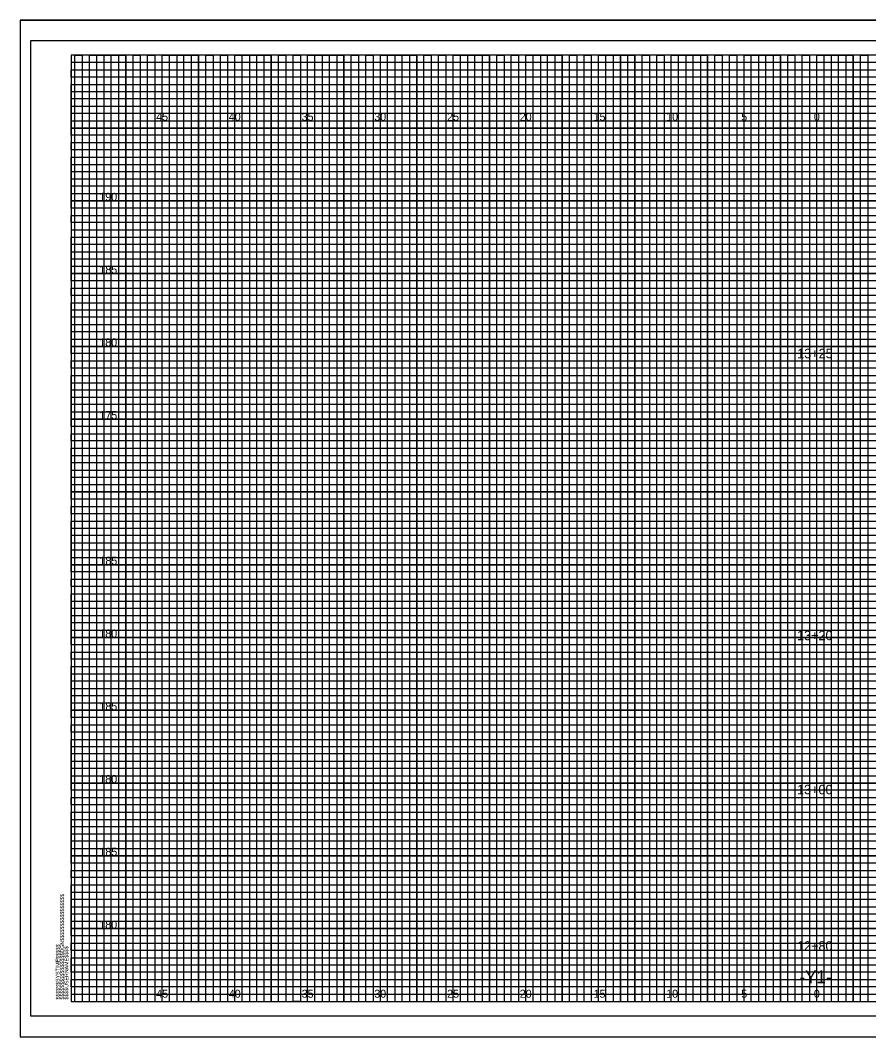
# Model space of a CAD drawing. Extents: x -4 to 103, y -2 to 209.
# Drawn here: x -3.5 to 54.8, y 68.4 to 138.2 of the extents above; entities that cross this region are included whole.
import ezdxf

# ---------------------------------------------------------------- set-up
doc = ezdxf.new("R2010")
doc.units = 0
for name, color, linetype in [('Old_Level_10', 7, 'Continuous'), ('Old_Level_16', 7, 'Continuous'), ('Old_Level_3', 7, 'Continuous'), ('Old_Level_4', 7, 'Continuous'), ('Old_Level_5', 7, 'Continuous'), ('Old_Level_6', 7, 'Continuous'), ('Old_Level_8', 7, 'Continuous'), ('Prop Dimension', 7, 'Continuous'), ('Prop XS Dump Level', 7, 'Continuous'), ('Prop XS Finish Grade Pavement', 7, 'Continuous'), ('Prop XS Subgrade Earthwork', 7, 'Continuous')]:
    doc.layers.add(name, color=color, linetype=linetype)

msp = doc.modelspace()

# ---------------------------------------------------------------- linework, layer by layer
at = {"layer": 'Old_Level_10'}
for p, q in [((1.25, 70.825), (1.25, 135.825)), ((3.75, 70.825), (3.75, 135.825)), ((6.25, 70.825), (6.25, 135.825)), ((8.75, 70.825), (8.75, 135.825)), ((11.25, 70.825), (11.25, 135.825)), ((13.75, 70.825), (13.75, 135.825)), ((16.25, 70.825), (16.25, 135.825)), ((18.75, 70.825), (18.75, 135.825)), ((21.25, 70.825), (21.25, 135.825)), ((23.75, 70.825), (23.75, 135.825)), ((26.25, 70.825), (26.25, 135.825)), ((28.75, 70.825), (28.75, 135.825)), ((31.25, 70.825), (31.25, 135.825)), ((33.75, 70.825), (33.75, 135.825)), ((36.25, 70.825), (36.25, 135.825)), ((38.75, 70.825), (38.75, 135.825)), ((41.25, 70.825), (41.25, 135.825)), ((43.75, 70.825), (43.75, 135.825)), ((46.25, 70.825), (46.25, 135.825)), ((48.75, 70.825), (48.75, 135.825)), ((51.25, 70.825), (51.25, 135.825)), ((53.75, 70.825), (53.75, 135.825)), ((0, 133.325), (74.25, 133.325)), ((0, 130.825), (102.5, 130.825)), ((0, 128.325), (102.5, 128.325)), ((0, 125.825), (102.5, 125.825)), ((0, 123.325), (102.5, 123.325)), ((0, 120.825), (102.5, 120.825)), ((0, 118.325), (102.5, 118.325)), ((0, 115.825), (102.5, 115.825)), ((0, 113.325), (102.5, 113.325)), ((0, 110.825), (102.5, 110.825)), ((0, 108.325), (102.5, 108.325)), ((0, 105.825), (102.5, 105.825)), ((0, 103.325), (102.5, 103.325)), ((0, 100.825), (102.5, 100.825)), ((0, 98.325), (102.5, 98.325)), ((0, 95.825), (102.5, 95.825)), ((0, 93.325), (102.5, 93.325)), ((0, 90.825), (102.5, 90.825)), ((0, 88.325), (102.5, 88.325)), ((0, 85.825), (102.5, 85.825)), ((0, 83.325), (102.5, 83.325)), ((0, 80.825), (102.5, 80.825)), ((0, 78.325), (102.5, 78.325)), ((0, 75.825), (102.5, 75.825)), ((0, 73.325), (102.5, 73.325))]:
    msp.add_line(p, q, dxfattribs=at)
at = {"layer": 'Old_Level_3'}
for p, q in [((-3.5, 138.225), (103.4, 138.225)), ((-3.5, 138.225), (-3.5, 68.4)), ((-3.5, 68.4), (103.4, 68.4))]:
    msp.add_line(p, q, dxfattribs=at)
at = {"layer": 'Old_Level_4'}
msp.add_lwpolyline([(103, 136.825), (-2.8, 136.825), (-2.8, 69.825), (103, 69.825)], close=True, dxfattribs=at)
at = {"layer": 'Old_Level_5'}
msp.add_lwpolyline([(103.4, 138.225), (-3.5, 138.225), (-3.5, 68.4), (103.4, 68.4)], close=True, dxfattribs=at)
at = {"layer": 'Old_Level_6'}
msp.add_lwpolyline([(102.5, 135.825), (0, 135.825), (0, 70.825), (102.5, 70.825)], close=True, dxfattribs=at)
at = {"layer": 'Old_Level_8'}
for points in [[(1.25, 70.825), (1.25, 135.825), (3.75, 135.825), (3.75, 70.825), (6.25, 70.825), (6.25, 135.825), (8.75, 135.825), (8.75, 70.825), (11.25, 70.825), (11.25, 135.825), (13.75, 135.825), (13.75, 70.825), (16.25, 70.825), (16.25, 135.825), (18.75, 135.825), (18.75, 70.825), (21.25, 70.825), (21.25, 135.825), (23.75, 135.825), (23.75, 70.825), (26.25, 70.825), (26.25, 135.825), (28.75, 135.825), (28.75, 70.825), (31.25, 70.825), (31.25, 135.825), (33.75, 135.825), (33.75, 70.825), (36.25, 70.825), (36.25, 135.825), (38.75, 135.825), (38.75, 70.825), (41.25, 70.825), (41.25, 135.825), (43.75, 135.825), (43.75, 70.825), (46.25, 70.825), (46.25, 135.825), (48.75, 135.825), (48.75, 70.825), (51.25, 70.825), (51.25, 135.825), (53.75, 135.825), (53.75, 70.825)], [(102.5, 130.825), (0, 130.825), (0, 133.325), (74.25, 133.325)], [(102.5, 125.825), (0, 125.825), (0, 128.325), (102.5, 128.325)], [(102.5, 120.825), (0, 120.825), (0, 123.325), (102.5, 123.325)], [(102.5, 115.825), (0, 115.825), (0, 118.325), (102.5, 118.325)], [(102.5, 110.825), (0, 110.825), (0, 113.325), (102.5, 113.325)], [(102.5, 105.825), (0, 105.825), (0, 108.325), (102.5, 108.325)], [(102.5, 100.825), (0, 100.825), (0, 103.325), (102.5, 103.325)], [(102.5, 95.825), (0, 95.825), (0, 98.325), (102.5, 98.325)], [(102.5, 90.825), (0, 90.825), (0, 93.325), (102.5, 93.325)], [(102.5, 85.825), (0, 85.825), (0, 88.325), (102.5, 88.325)], [(102.5, 80.825), (0, 80.825), (0, 83.325), (102.5, 83.325)], [(102.5, 75.825), (0, 75.825), (0, 78.325), (102.5, 78.325)], [(0, 73.325), (102.5, 73.325)]]:
    msp.add_lwpolyline(points, dxfattribs=at)
at = {"layer": 'Prop Dimension'}
for points in [[(0.25, 70.825), (0.25, 135.825), (0.75, 135.825), (0.75, 70.825), (1.75, 70.825), (1.75, 135.825), (2.25, 135.825), (2.25, 70.825), (2.75, 70.825), (2.75, 135.825), (3.25, 135.825), (3.25, 70.825), (4.25, 70.825), (4.25, 135.825), (4.75, 135.825), (4.75, 70.825), (5.25, 70.825), (5.25, 135.825), (5.75, 135.825), (5.75, 70.825), (6.75, 70.825), (6.75, 135.825), (7.25, 135.825), (7.25, 70.825), (7.75, 70.825), (7.75, 135.825), (8.25, 135.825), (8.25, 70.825), (9.25, 70.825), (9.25, 135.825), (9.75, 135.825), (9.75, 70.825), (10.25, 70.825), (10.25, 135.825), (10.75, 135.825), (10.75, 70.825), (11.75, 70.825), (11.75, 135.825), (12.25, 135.825), (12.25, 70.825), (12.75, 70.825), (12.75, 135.825), (13.25, 135.825), (13.25, 70.825), (14.25, 70.825), (14.25, 135.825), (14.75, 135.825), (14.75, 70.825), (15.75, 70.825), (15.25, 70.825), (15.25, 135.825), (15.75, 135.825), (15.75, 70.825), (16.75, 70.825), (16.75, 135.825), (17.25, 135.825), (17.25, 70.825), (17.75, 70.825), (17.75, 135.825), (18.25, 135.825), (18.25, 70.825), (19.25, 70.825), (19.25, 135.825), (19.75, 135.825), (19.75, 70.825), (20.25, 70.825), (20.25, 135.825), (20.75, 135.825), (20.75, 70.825), (21.75, 70.825), (21.75, 135.825), (22.25, 135.825), (22.25, 70.825), (22.75, 70.825), (22.75, 135.825), (23.25, 135.825), (23.25, 70.825), (24.25, 70.825), (24.25, 135.825), (24.75, 135.825), (24.75, 70.825), (25.25, 70.825), (25.25, 135.825), (25.75, 135.825), (25.75, 70.825), (26.75, 70.825), (26.75, 135.825), (27.25, 135.825), (27.25, 70.825), (27.75, 70.825), (27.75, 135.825), (28.25, 135.825), (28.25, 70.825), (29.25, 70.825), (29.25, 135.825), (29.75, 135.825), (29.75, 70.825), (30.25, 70.825), (30.25, 135.825), (30.75, 135.825), (30.75, 70.825)], [(30.75, 70.825), (31.75, 70.825), (31.75, 135.825), (32.25, 135.825), (32.25, 70.825), (32.75, 70.825), (32.75, 135.825), (33.25, 135.825), (33.25, 70.825), (34.25, 70.825), (34.25, 135.825), (34.75, 135.825), (34.75, 70.825), (35.25, 70.825), (35.25, 135.825), (35.75, 135.825), (35.75, 70.825), (36.75, 70.825), (36.75, 135.825), (37.25, 135.825), (37.25, 70.825), (37.75, 70.825), (37.75, 135.825), (37.75, 70.825)], [(38.25, 135.825), (38.25, 70.825), (39.25, 70.825), (39.25, 135.825), (39.75, 135.825), (39.75, 70.825), (40.25, 70.825), (40.25, 135.825), (40.75, 135.825), (40.75, 70.825), (41.75, 70.825), (41.75, 135.825), (42.25, 135.825), (42.25, 70.825), (42.75, 70.825), (42.75, 135.825), (43.25, 135.825), (43.25, 70.825), (43.75, 70.825), (44.25, 70.825), (44.25, 135.825), (44.75, 135.825), (44.75, 70.825), (45.25, 70.825), (45.25, 135.825), (45.75, 135.825), (45.75, 70.825), (46.75, 70.825), (46.75, 135.825), (47.25, 135.825), (47.25, 70.825), (47.75, 70.825), (47.75, 135.825), (48.25, 135.825), (48.25, 70.825), (49.25, 70.825), (49.25, 135.825), (49.75, 135.825), (49.75, 70.825), (50.25, 70.825), (50.25, 135.825), (50.75, 135.825), (50.75, 70.825), (51.75, 70.825), (51.75, 135.825), (52.25, 135.825), (52.25, 70.825), (52.75, 70.825), (52.75, 135.825), (53.25, 135.825), (53.25, 70.825), (54.25, 70.825), (54.25, 135.825), (54.75, 135.825), (54.75, 70.825), (55.25, 70.825)], [(0, 132.825), (0, 133.825), (74.25, 133.825), (74.25, 134.325), (0, 134.325), (0, 134.825), (74.25, 134.825), (74.25, 135.325), (0, 135.325)], [(102.5, 132.825), (0, 132.825)], [(102.5, 131.825), (0, 131.825), (0, 132.325), (102.5, 132.325)], [(102.5, 130.325), (0, 130.325), (0, 131.325), (102.5, 131.325)], [(102.5, 129.325), (0, 129.325), (0, 129.825), (102.5, 129.825)], [(102.5, 127.825), (0, 127.825), (0, 128.825), (102.5, 128.825)], [(102.5, 126.825), (0, 126.825), (0, 127.325), (102.5, 127.325)], [(102.5, 125.325), (0, 125.325), (0, 126.325), (102.5, 126.325)], [(102.5, 124.325), (0, 124.325), (0, 124.825), (102.5, 124.825)], [(0, 123.825), (102.5, 123.825)], [(102.5, 122.825), (0, 122.825)], [(102.5, 121.825), (0, 121.825), (0, 122.325), (102.5, 122.325)], [(102.5, 120.325), (0, 120.325), (0, 121.325), (102.5, 121.325)], [(102.5, 119.325), (0, 119.325), (0, 119.825), (102.5, 119.825)], [(102.5, 117.825), (0, 117.825), (0, 118.825), (102.5, 118.825)], [(102.5, 116.825), (0, 116.825), (0, 117.325), (102.5, 117.325)], [(102.5, 115.325), (0, 115.325), (0, 116.325), (102.5, 116.325)], [(102.5, 114.325), (0, 114.325), (0, 114.825), (102.5, 114.825)], [(102.5, 112.825), (0, 112.825), (0, 113.825), (102.5, 113.825)], [(102.5, 111.825), (0, 111.825), (0, 112.325), (102.5, 112.325)], [(102.5, 110.325), (0, 110.325), (0, 111.325), (102.5, 111.325)], [(102.5, 109.325), (0, 109.325), (0, 109.825), (102.5, 109.825)], [(102.5, 107.825), (0, 107.825), (0, 108.825), (102.5, 108.825)], [(102.5, 106.825), (0, 106.825), (0, 107.325), (102.5, 107.325)], [(102.5, 105.325), (0, 105.325), (0, 106.325), (102.5, 106.325)], [(102.5, 104.325), (0, 104.325), (0, 104.825), (102.5, 104.825)], [(102.5, 102.825), (0, 102.825), (0, 103.825), (102.5, 103.825)], [(102.5, 101.825), (0, 101.825), (0, 102.325)], [(0, 102.325), (102.5, 102.325)], [(102.5, 100.325), (0, 100.325), (0, 101.325), (102.5, 101.325)], [(102.5, 99.325), (0, 99.325), (0, 99.825), (102.5, 99.825)], [(102.5, 97.825), (0, 97.825), (0, 98.825), (102.5, 98.825)], [(102.5, 96.825), (0, 96.825), (0, 97.325), (102.5, 97.325)], [(102.5, 95.325), (0, 95.325), (0, 96.325), (102.5, 96.325)], [(102.5, 94.325), (0, 94.325), (0, 94.825), (102.5, 94.825)], [(102.5, 92.825), (0, 92.825), (0, 93.825), (102.5, 93.825)], [(102.5, 91.825), (0, 91.825), (0, 92.325), (102.5, 92.325)], [(102.5, 90.325), (0, 90.325), (0, 91.325), (102.5, 91.325)], [(102.5, 89.325), (0, 89.325), (0, 89.825), (102.5, 89.825)], [(102.5, 87.825), (0, 87.825), (0, 88.825), (102.5, 88.825)], [(102.5, 86.825), (0, 86.825), (0, 87.325), (102.5, 87.325)], [(102.5, 85.325), (0, 85.325), (0, 86.325), (102.5, 86.325)], [(102.5, 84.325), (0, 84.325), (0, 84.825), (102.5, 84.825)], [(102.5, 82.825), (0, 82.825), (0, 83.825), (102.5, 83.825)], [(102.5, 81.825), (0, 81.825), (0, 82.325), (102.5, 82.325)], [(102.5, 80.325), (0, 80.325), (0, 81.325), (102.5, 81.325)], [(102.5, 79.325), (0, 79.325), (0, 79.825), (102.5, 79.825)], [(102.5, 77.825), (0, 77.825), (0, 78.825), (102.5, 78.825)], [(102.5, 76.825), (0, 76.825), (0, 77.325), (102.5, 77.325)], [(102.5, 75.325), (0, 75.325), (0, 76.325), (102.5, 76.325)], [(102.5, 74.325), (0, 74.325), (0, 74.825), (102.5, 74.825)], [(102.5, 72.825), (0, 72.825), (0, 73.825), (102.5, 73.825)], [(102.5, 71.825), (0, 71.825), (0, 72.325), (102.5, 72.325)], [(0, 71.325), (102.5, 71.325)]]:
    msp.add_lwpolyline(points, dxfattribs=at)

# ---------------------------------------------------------------- texts
at = {"layer": 'Old_Level_16'}
for s, p in [('45', (5.8399, 131.325)), ('40', (10.8313, 131.325)), ('35', (15.8399, 131.325)), ('30', (20.8313, 131.325)), ('25', (25.8399, 131.325)), ('20', (30.8313, 131.325)), ('15', (35.9058, 131.325)), ('10', (40.8971, 131.325)), ('5', (46.0574, 131.325)), ('0', (51.0488, 131.325)), ('0', (51.0488, 131.325)), ('45', (5.8399, 71.075)), ('40', (10.8313, 71.075)), ('35', (15.8399, 71.075)), ('30', (20.8313, 71.075)), ('25', (25.8399, 71.075)), ('20', (30.8313, 71.075)), ('15', (35.9058, 71.075)), ('10', (40.8971, 71.075)), ('5', (46.0574, 71.075)), ('0', (51.0488, 71.075)), ('0', (51.0488, 71.075))]:
    msp.add_text(s, height=0.55, dxfattribs=at).set_placement(p)
at = {"layer": 'Old_Level_6'}
for s, p in [('$$$$$$$$$$$$$$$$DGN$$$$$$$$$$$$$$$$', (-0.5, 70.95)), ('$$$$$$SYSTIME$$$$$', (-0.7973, 70.9497)), ('$$$$USERNAME$$$$', (-0.2, 70.95))]:
    msp.add_text(s, height=0.2625, rotation=90, dxfattribs=at).set_placement(p)
at = {"layer": 'Old_Level_8'}
msp.add_text('040397', height=0.0025, rotation=90, dxfattribs=at).set_placement((-0.0007, 135.8114))
at = {"layer": 'Prop XS Dump Level'}
msp.add_text('-Y1-', height=0.875, dxfattribs=at).set_placement((50.0581, 72.075))
at = {"layer": 'Prop XS Finish Grade Pavement'}
for s, p in [('13+25', (49.9036, 115.0104)), ('13+20', (49.8934, 95.6395)), ('13+00', (49.8934, 85.0517)), ('12+80', (49.8934, 74.3046))]:
    msp.add_text(s, height=0.65, dxfattribs=at).set_placement(p)
at = {"layer": 'Prop XS Subgrade Earthwork'}
for s, p in [('190', (1.9296, 125.825)), ('185', (1.9383, 120.825)), ('180', (1.9296, 115.825)), ('175', (1.9383, 110.825)), ('185', (1.9383, 100.825)), ('180', (1.9296, 95.825)), ('185', (1.9383, 90.825)), ('180', (1.9296, 85.825)), ('185', (1.9383, 80.825)), ('180', (1.9296, 75.825))]:
    msp.add_text(s, height=0.55, dxfattribs=at).set_placement(p)

doc.saveas('drawing.dxf')
